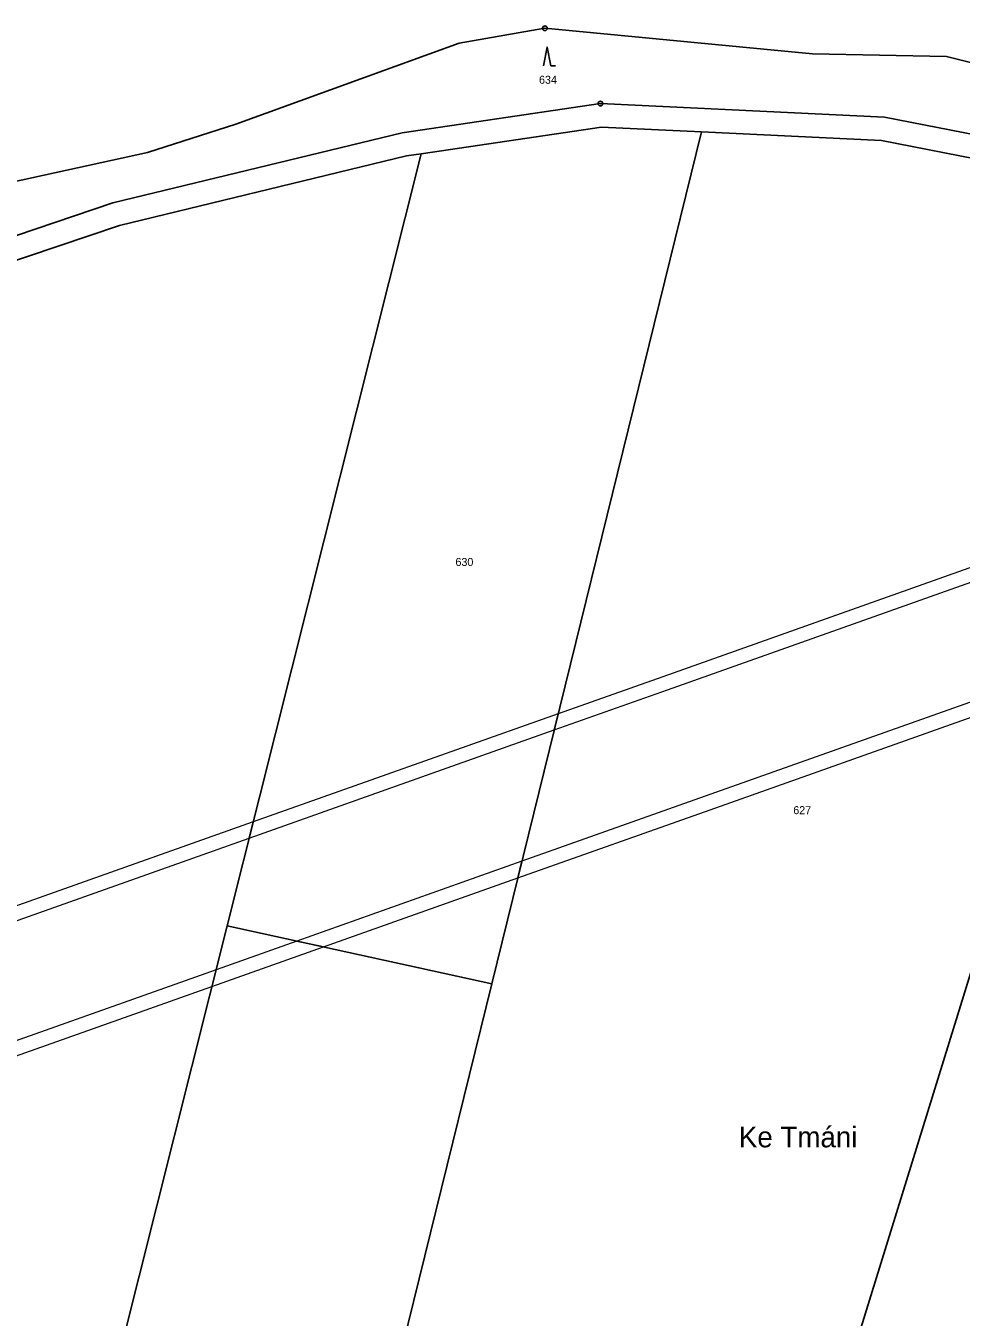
# Model space of a CAD drawing. Extents: x -759947 to -757003, y -1019641 to -1017100.
# Drawn here: x -759425.7 to -759227.1, y -1018952.6 to -1018678.3 of the extents above; entities that cross this region are included whole.
import ezdxf

# ---------------------------------------------------------------- set-up
doc = ezdxf.new("R2010")
doc.units = 0
doc.header["$LTSCALE"] = 0.68
for name, color, linetype, lineweight in [('1', 7, 'Continuous', 25), ('13', 7, 'Continuous', 13), ('3', 7, 'Continuous', 25), ('7', 7, 'Continuous', 13), ('8', 7, 'Continuous', 25)]:
    doc.layers.add(name, color=color, linetype=linetype, lineweight=lineweight)
doc.layers.add('2', color=7, linetype='Continuous')

msp = doc.modelspace()

# ---------------------------------------------------------------- linework, layer by layer
at = {"layer": '1'}
for p, q in [((-759333.72, -1018682.03), (-759315.46, -1018678.82)), ((-759315.46, -1018678.82), (-759258.62, -1018684.28)), ((-759381.11, -1018699.2), (-759333.72, -1018682.03)), ((-759258.62, -1018684.28), (-759230.15, -1018684.87)), ((-759230.15, -1018684.87), (-759187.43, -1018695.44)), ((-759303.69, -1018694.85), (-759345.79, -1018701.04)), ((-759243.35, -1018697.69), (-759303.69, -1018694.85)), ((-759399.9, -1018705.25), (-759381.11, -1018699.2)), ((-759183.22, -1018709.59), (-759243.35, -1018697.69)), ((-759407.24, -1018715.92), (-759345.79, -1018701.04)), ((-759341.76, -1018705.5), (-759303.44, -1018699.87)), ((-759282.23, -1018700.87), (-759326.75, -1018881.81)), ((-759303.44, -1018699.87), (-759282.23, -1018700.87)), ((-759282.23, -1018700.87), (-759243.96, -1018702.67)), ((-759243.96, -1018702.67), (-759184.39, -1018714.46)), ((-759435.07, -1018712.94), (-759399.9, -1018705.25)), ((-759405.85, -1018720.73), (-759344.84, -1018705.95)), ((-759382.97, -1018869.53), (-759341.76, -1018705.5)), ((-759344.84, -1018705.95), (-759341.76, -1018705.5)), ((-759486.92, -1018742.87), (-759407.24, -1018715.92)), ((-759485.8, -1018747.77), (-759405.85, -1018720.73)), ((-759216.51, -1018851.88), (-759258.18, -1018986.59)), ((-759417.24, -1019005.94), (-759382.97, -1018869.53)), ((-759326.75, -1018881.81), (-759382.97, -1018869.53)), ((-759326.75, -1018881.81), (-759347.77, -1018967.21))]:
    msp.add_line(p, q, dxfattribs=at)
at = {"layer": '13'}
for points in [[(-759195.13, -1018782.76), (-759290.45, -1018816.58), (-759312.64, -1018824.45), (-759313.49, -1018827.9), (-759289.43, -1018819.37), (-759196.23, -1018786.31)], [(-759205.08, -1018814.92), (-759281.41, -1018841.99), (-759320.35, -1018855.8), (-759321.22, -1018859.33), (-759280.35, -1018844.83), (-759206.19, -1018818.52)], [(-759378.29, -1018850.89), (-759313.49, -1018827.9), (-759312.64, -1018824.45), (-759377.42, -1018847.44)], [(-759377.42, -1018847.44), (-759559.58, -1018912.07), (-759560.26, -1018915.46), (-759378.29, -1018850.89)], [(-759362.54, -1018873.99), (-759321.22, -1018859.33), (-759320.35, -1018855.8), (-759368.15, -1018872.77)], [(-759368.15, -1018872.77), (-759385.31, -1018878.86), (-759565.78, -1018942.89), (-759566.47, -1018946.34), (-759386.2, -1018882.38), (-759362.54, -1018873.99)]]:
    msp.add_lwpolyline(points, close=True, dxfattribs=at)
at = {"layer": '3'}
msp.add_line((-759314.25, -1018686.83), (-759313.254, -1018686.83), dxfattribs=at)
msp.add_lwpolyline([(-759314.25, -1018686.83), (-759315, -1018682.83), (-759315.75, -1018686.83)], dxfattribs=at)
at = {"layer": '8'}
for centre, radius in [((-759315.46, -1018678.8199), 0.5), ((-759315.46, -1018678.8199), 0.0303), ((-759303.69, -1018694.8499), 0.5), ((-759303.69, -1018694.8499), 0.0303)]:
    msp.add_circle(centre, radius, dxfattribs=at)

# ---------------------------------------------------------------- texts
at = {"layer": '2'}
for s, p in [('634', (-759316.72, -1018690.625)), ('630', (-759334.47, -1018793.055)), ('627', (-759262.71, -1018845.785))]:
    msp.add_text(s, height=1.7, dxfattribs=at).set_placement(p)
at = {"layer": '7'}
msp.add_text('Ke Tmáni', height=4.4, dxfattribs=at).set_placement((-759274.27, -1018916.56))

doc.saveas('drawing.dxf')
